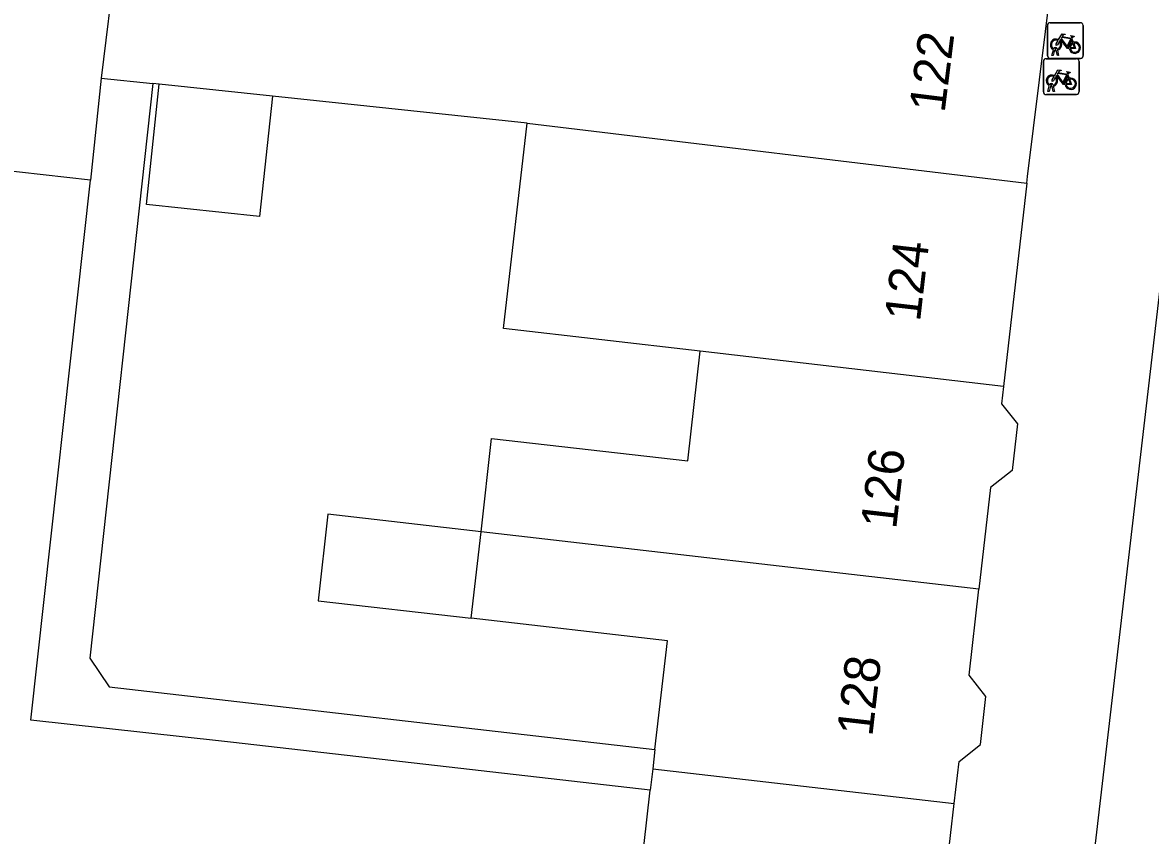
# Model space of a CAD drawing. Extents: x 161696 to 162377, y 380761 to 381673.
# Drawn here: x 162248.14 to 162279.68, y 381154.7 to 381177.42 of the extents above; entities that cross this region are included whole.
import ezdxf

# ---------------------------------------------------------------- set-up
doc = ezdxf.new("R2010")
doc.units = 0
for name, color, linetype in [('IMGEO_Fietsenrek', 7, 'Continuous'), ('IMGEO_Pand', 7, 'Continuous'), ('IMGEO_Pand_nummerreeks', 7, 'Continuous'), ('IMGEO_Voetpad_open', 7, 'Continuous')]:
    doc.layers.add(name, color=color, linetype=linetype)

msp = doc.modelspace()

# ---------------------------------------------------------------- linework, layer by layer
at = {"layer": 'IMGEO_Fietsenrek'}
for p, q in [((162276.8, 381176.491), (162276.8, 381177.332)), ((162276.8, 381177.332), (162276.8, 381176.491)), ((162276.875, 381177.416), (162277.716, 381177.416)), ((162277.716, 381177.416), (162276.875, 381177.416)), ((162277.8, 381177.341), (162277.8, 381176.5)), ((162277.8, 381176.5), (162277.8, 381177.341)), ((162277.487, 381176.965), (162277.523, 381176.87)), ((162276.927, 381176.5), (162276.966, 381176.66)), ((162276.996, 381176.648), (162276.961, 381176.5)), ((162277.038, 381176.672), (162277.037, 381176.676)), ((162277.079, 381176.5), (162277.045, 381176.642)), ((162277.069, 381176.683), (162277.07, 381176.676)), ((162277.077, 381176.646), (162277.112, 381176.5)), ((162276.686, 381175.484), (162276.686, 381176.325)), ((162276.686, 381176.325), (162276.686, 381175.484)), ((162276.761, 381176.409), (162277.602, 381176.409)), ((162277.602, 381176.409), (162276.761, 381176.409)), ((162277.725, 381176.416), (162276.884, 381176.416)), ((162276.884, 381176.416), (162277.725, 381176.416)), ((162276.961, 381176.5), (162276.927, 381176.5)), ((162277.112, 381176.5), (162277.079, 381176.5)), ((162277.686, 381176.334), (162277.686, 381175.493)), ((162277.686, 381175.493), (162277.686, 381176.334)), ((162276.813, 381175.493), (162276.852, 381175.653)), ((162276.924, 381175.665), (162276.923, 381175.669)), ((162276.955, 381175.676), (162276.956, 381175.669)), ((162277.373, 381175.958), (162277.409, 381175.863)), ((162277.611, 381175.409), (162276.77, 381175.409)), ((162276.77, 381175.409), (162277.611, 381175.409)), ((162276.847, 381175.493), (162276.813, 381175.493)), ((162276.882, 381175.641), (162276.847, 381175.493)), ((162276.965, 381175.493), (162276.931, 381175.635)), ((162276.963, 381175.639), (162276.998, 381175.493)), ((162276.998, 381175.493), (162276.965, 381175.493))]:
    msp.add_line(p, q, dxfattribs=at)
for points in [[(162277.134, 381176.89), (162277.082, 381176.8), (162277.042, 381176.775), (162277.043, 381176.822), (162277.098, 381176.916)], [(162277.113, 381176.942), (162277.208, 381177.106), (162277.294, 381177.092), (162277.296, 381177.083), (162277.24, 381177.072), (162277.213, 381177.027), (162277.469, 381176.986)], [(162277.409, 381176.698), (162277.359, 381176.698), (162277.168, 381176.949), (162277.149, 381176.917)], [(162277.456, 381176.961), (162277.199, 381177.002), (162277.182, 381176.973), (162277.349, 381176.753), (162277.456, 381176.961)], [(162277.504, 381176.863), (162277.474, 381176.94), (162277.365, 381176.722), (162277.408, 381176.722)], [(162277.469, 381176.986), (162277.494, 381177.035), (162277.488, 381177.039), (162277.465, 381177.043), (162277.453, 381177.05), (162277.452, 381177.053), (162277.454, 381177.058), (162277.549, 381177.043), (162277.551, 381177.033), (162277.541, 381177.02), (162277.529, 381177.014), (162277.515, 381177.02), (162277.487, 381176.965)], [(162277.438, 381176.722), (162277.558, 381176.721), (162277.514, 381176.835)], [(162277.534, 381176.842), (162277.589, 381176.697), (162277.439, 381176.697)], [(162276.999, 381175.935), (162277.094, 381176.099), (162277.18, 381176.085), (162277.182, 381176.076), (162277.126, 381176.065), (162277.099, 381176.02), (162277.355, 381175.979)], [(162277.342, 381175.954), (162277.085, 381175.995), (162277.068, 381175.966), (162277.235, 381175.746), (162277.342, 381175.954)], [(162277.355, 381175.979), (162277.38, 381176.028), (162277.374, 381176.032), (162277.351, 381176.036), (162277.339, 381176.043), (162277.338, 381176.046), (162277.34, 381176.051), (162277.435, 381176.036), (162277.437, 381176.026), (162277.427, 381176.013), (162277.415, 381176.007), (162277.401, 381176.013), (162277.373, 381175.958)], [(162277.02, 381175.883), (162276.968, 381175.793), (162276.928, 381175.768), (162276.929, 381175.815), (162276.984, 381175.909)], [(162277.295, 381175.691), (162277.245, 381175.691), (162277.054, 381175.942), (162277.035, 381175.91)], [(162277.39, 381175.856), (162277.36, 381175.933), (162277.251, 381175.715), (162277.294, 381175.715)], [(162277.324, 381175.715), (162277.444, 381175.714), (162277.4, 381175.828)], [(162277.42, 381175.835), (162277.475, 381175.69), (162277.325, 381175.69)]]:
    msp.add_lwpolyline(points, dxfattribs=at)
for centre, radius, start, end in [((162276.878, 381177.338), 0.0779, 92.4484, 184.2845), ((162276.878, 381177.338), 0.0779, 92.4484, 184.2845), ((162277.722, 381177.338), 0.0779, 2.4484, 94.2845), ((162277.722, 381177.338), 0.0779, 2.4484, 94.2845), ((162277.04, 381176.801), 0.159, 62.6766, 242.1369), ((162277.04, 381176.801), 0.129, 63.3192, 238.903), ((162277.04, 381176.801), 0.159, 283.5766, 46.6042), ((162277.02, 381176.672), 0.0499, 12.8025, 158.6934), ((162277.04, 381176.801), 0.159, 253.9967, 271.7867), ((162277.02, 381176.672), 0.0174, 12.8025, 163.4502), ((162277.04, 381176.801), 0.129, 253.415, 269.0204), ((162277.04, 381176.801), 0.129, 283.6043, 43.4302), ((162277.567, 381176.717), 0.159, 113.3408, 178.3217), ((162277.567, 381176.717), 0.159, 187.0065, 105.7708), ((162277.567, 381176.717), 0.129, 113.923, 177.9556), ((162277.567, 381176.717), 0.129, 188.6715, 104.5883), ((162276.764, 381176.331), 0.0779, 92.4484, 184.2845), ((162276.764, 381176.331), 0.0779, 92.4484, 184.2845), ((162276.878, 381176.494), 0.0779, 182.4484, 274.2845), ((162276.878, 381176.494), 0.0779, 182.4484, 274.2845), ((162277.608, 381176.331), 0.0779, 2.4484, 94.2845), ((162277.608, 381176.331), 0.0779, 2.4484, 94.2845), ((162277.722, 381176.494), 0.0779, 272.4484, 4.2845), ((162277.722, 381176.494), 0.0779, 272.4484, 4.2845), ((162276.926, 381175.794), 0.159, 62.6766, 242.1369), ((162276.926, 381175.794), 0.129, 63.3192, 238.903), ((162276.906, 381175.665), 0.0499, 12.8025, 158.6934), ((162276.906, 381175.665), 0.0174, 12.8025, 163.4502), ((162276.926, 381175.794), 0.129, 253.415, 269.0204), ((162276.926, 381175.794), 0.129, 283.6043, 43.4302), ((162276.926, 381175.794), 0.159, 283.5766, 46.6042), ((162277.453, 381175.71), 0.159, 113.3408, 178.3217), ((162277.453, 381175.71), 0.159, 187.0065, 105.7708), ((162277.453, 381175.71), 0.129, 113.923, 177.9556), ((162277.453, 381175.71), 0.129, 188.6715, 104.5883), ((162276.764, 381175.487), 0.0779, 182.4484, 274.2845), ((162276.764, 381175.487), 0.0779, 182.4484, 274.2845), ((162276.926, 381175.794), 0.159, 253.9967, 271.7867), ((162277.608, 381175.487), 0.0779, 272.4484, 4.2845), ((162277.608, 381175.487), 0.0779, 272.4484, 4.2845)]:
    msp.add_arc(centre, radius, start, end, dxfattribs=at)
at = {"layer": 'IMGEO_Pand'}
for points in [[(162251.152, 381181.506), (162250.858, 381179.12), (162250.742, 381179.133), (162250.337, 381175.869)], [(162276.221, 381172.929), (162276.243, 381173.117), (162276.917, 381178.53)], [(162250.337, 381175.869), (162250.038, 381173.015)], [(162250.337, 381175.869), (162251.787, 381175.715)], [(162255.127, 381175.36), (162254.769, 381171.998), (162251.607, 381172.334), (162251.964, 381175.696)], [(162251.964, 381175.696), (162251.787, 381175.715)], [(162255.127, 381175.36), (162251.964, 381175.696)], [(162262.247, 381174.603), (162255.127, 381175.36)], [(162267.093, 381168.234), (162261.59, 381168.864), (162262.247, 381174.603)], [(162262.247, 381174.603), (162276.221, 381172.929)], [(162250.038, 381173.015), (162243.409, 381173.762), (162242.998, 381173.808)], [(162276.221, 381172.929), (162275.569, 381167.247)], [(162260.96, 381163.187), (162261.258, 381165.795), (162266.742, 381165.167), (162267.093, 381168.234)], [(162275.569, 381167.247), (162267.093, 381168.234)], [(162275.569, 381167.247), (162275.513, 381166.763), (162275.96, 381166.2), (162275.811, 381164.901), (162275.211, 381164.424), (162274.885, 381161.578)], [(162260.96, 381163.187), (162256.68, 381163.681), (162256.403, 381161.258), (162260.683, 381160.768)], [(162260.683, 381160.768), (162260.96, 381163.187)], [(162274.885, 381161.578), (162260.96, 381163.187)], [(162274.194, 381155.588), (162274.328, 381156.762), (162274.925, 381157.236), (162275.079, 381158.582), (162274.61, 381159.173), (162274.885, 381161.578)], [(162265.825, 381157.098), (162266.174, 381160.139), (162260.683, 381160.768)], [(162265.825, 381157.098), (162265.764, 381156.562)], [(162265.764, 381156.562), (162265.695, 381155.962)], [(162265.764, 381156.562), (162274.194, 381155.588)], [(162262.13, 381150.621), (162259.553, 381150.916), (162259.852, 381153.527), (162265.345, 381152.898), (162265.695, 381155.962)], [(162273.477, 381149.329), (162274.194, 381155.588)]]:
    msp.add_lwpolyline(points, dxfattribs=at)
at = {"layer": 'IMGEO_Voetpad_open'}
for points in [[(162275.499, 381131.748), (162280.246, 381172.46), (162284.2, 381207.225)], [(162251.787, 381175.715), (162250.017, 381159.649), (162250.564, 381158.847), (162265.825, 381157.098)], [(162265.695, 381155.962), (162254.042, 381157.295), (162253.7, 381157.333), (162248.372, 381157.92), (162250.038, 381173.015)]]:
    msp.add_lwpolyline(points, dxfattribs=at)

# ---------------------------------------------------------------- texts
at = {"layer": 'IMGEO_Pand_nummerreeks'}
for s, rotation, p in [('122', 82.9127, (162273.924, 381174.878)), ('124', 83.432, (162273.236, 381169.039)), ('126', 83.432, (162272.568, 381163.239)), ('128', 83.4341, (162271.902, 381157.442))]:
    msp.add_text(s, height=1, rotation=rotation, dxfattribs=at).set_placement(p)

doc.saveas('drawing.dxf')
